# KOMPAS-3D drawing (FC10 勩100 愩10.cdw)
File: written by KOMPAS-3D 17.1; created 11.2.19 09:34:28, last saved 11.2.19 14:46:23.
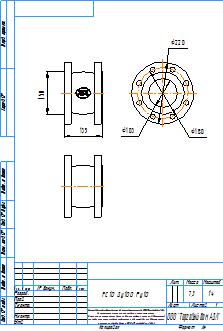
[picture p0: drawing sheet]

Sheet 1: A4, portrait

Title block, sheet 1: name: FC10 Ду100 Ру10; mass: 7,3; sheets: 1; sheet format: A4; stored path: \\adlc.lan\data\АДЛ_ПКД\3D-модели\ADL production\Гибкие вставки серии FC\FC10\KOMPAS 2D\FC10 Ду100 Ру10.cdw

Views: Вид 1
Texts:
  kka
  adl
  Рама для чертежей
  Лит-Масса-Масштаб
  Материал-Предприятие
  Масштаб
  Изм.
  Лист
  № докум.
  Подп.
  Дата
  Лит.
  Разраб.
  Пров.
  Т.контр.
  Листов
  Внимание! Данный продукт является объектом авторского права ООО «Торговый Дом АДЛ».
  Запрещается изменение, копирование, распространение
  (в том числе путем копирования на другие сайты и ресурсы в Интернете)
  или любое иное использование информации и объектов без предварительного
  согласия правообладателя (ООО «Торговый Дом АДЛ»).
  Н.контр.
  Утв.
  ООО "Торговый дом АДЛ"
  Изменение
  Номер документа
  Подпись
  Обозначение документа
  Наименование изделия
  Масса изделия по ГОСТ 2.109-73
  Порядковый номер листа
  Общее количество листов в документе
  Характер работы, выполненной лицом, подписавшим документ
  Наименование или индекс предприятия, выпускающего документ
  Инв. № подл.
  Подп. и дата
  Взам. инв. №
  Инв. № дубл.
  Инвентарный номер подлинника по ГОСТ 2.501-68
  Подпись принявшего подлинник в отдел технической документации
  Инвентарный номер подлинника, взамен которого выпущен данный подлинник
  Инвентарный номер дубликата по ГОСТ 2.502-68
  Подпись принявшего дубликат в отдел технической документации
  Справ. №
  Перв. примен.
  Обозначение документа, взамен или на основании которого выпущен данный документ
  Обозначение документа, в котором впервые записан данный документ
  Подпись лица, копировавшего чертеж
  Обозначение формата листа
  !Рама для чертежа
Dimensions and other numbers on the sheet: 135; 150; 103; 220; 180; 1:4; 1; 7,3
